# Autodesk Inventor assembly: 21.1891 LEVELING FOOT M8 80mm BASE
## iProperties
Created: 2007-03
Part Number: 21.1891 LEVELING FOOT M8 80mm BASE
Document SubType Name: Assembly
Designer: Andy Moles
Author: Andy Moles
